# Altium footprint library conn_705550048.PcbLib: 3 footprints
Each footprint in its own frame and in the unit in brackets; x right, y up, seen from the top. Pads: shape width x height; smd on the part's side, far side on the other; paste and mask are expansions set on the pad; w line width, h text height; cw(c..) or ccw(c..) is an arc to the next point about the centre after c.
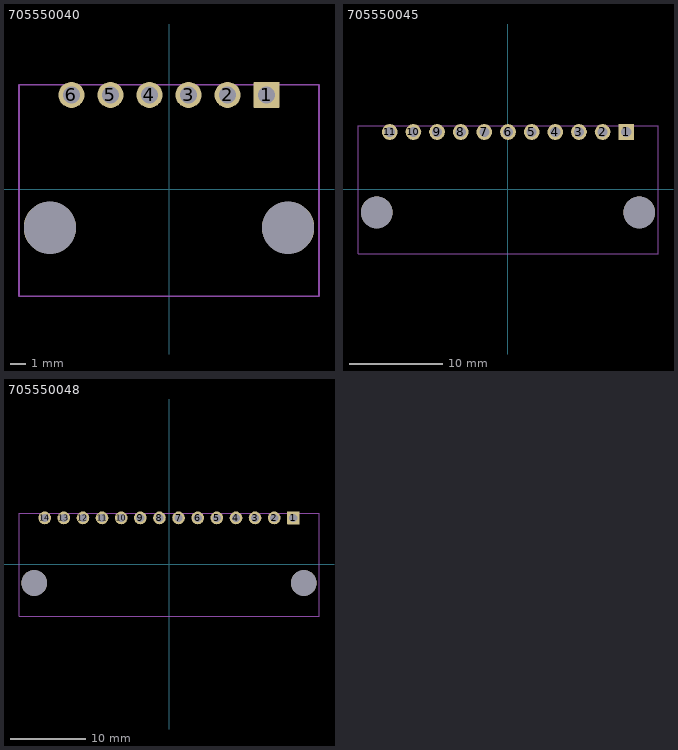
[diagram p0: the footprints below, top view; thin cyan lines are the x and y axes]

## 705550040 [mm]
height 1.1
pads (8):
  rrect6% 1.69x1.69 hole 1.09 paste-1000 mask+0: 1(6.35,6.145)
  round 1.69 hole 1.09 paste-1000 mask+0: 2(3.81,6.145) 3(1.27,6.145) 4(-1.27,6.145) 5(-3.81,6.145) 6(-6.35,6.145)
  round 3.4 hole 3.4 unplated paste-1000 mask+0: ""(-7.75,-2.495) ""(7.75,-2.495)
Mechanical 5:
  lines w0.1: -9.76,-6.945 -9.76,6.795 9.76,6.795 9.76,-6.945 -9.76,-6.945
  text ".Designator" at 0,0.022 h0.5
3D body "705550040.stp": height 7.12, standoff -3.17, extent -9.525,-6.789 9.525,6.8

## 705550045 [mm]
height 1.1
pads (13):
  rrect6% 1.69x1.69 hole 1.09 paste-1000 mask+0: 1(12.71,6.145)
  round 1.69 hole 1.09 paste-1000 mask+0: 2(10.17,6.145) 3(7.63,6.145) 4(5.09,6.145) 5(2.55,6.145) 6(0.01,6.145) 7(-2.53,6.145) 8(-5.07,6.145) 9(-7.61,6.145) 10(-10.15,6.145) 11(-12.69,6.145)
  round 3.4 hole 3.4 unplated paste-1000 mask+0: ""(-14.09,-2.495) ""(14.11,-2.495)
Mechanical 5:
  lines w0.1: -16.1,-6.945 -16.1,6.795 16.12,6.795 16.12,-6.945 -16.1,-6.945
  text ".Designator" at -3.8,0.022 h0.5
3D body "705550045.stp": height 7.11, standoff -3.17, extent -15.875,-6.789 15.875,6.8

## 705550048 [mm]
height 1.1
pads (16):
  rrect6% 1.69x1.69 hole 1.09 paste-1000 mask+0: 1(16.51,6.145)
  round 1.69 hole 1.09 paste-1000 mask+0: 2(13.97,6.145) 3(11.43,6.145) 4(8.89,6.145) 5(6.35,6.145) 6(3.81,6.145) 7(1.27,6.145) 8(-1.27,6.145) 9(-3.81,6.145) 10(-6.35,6.145) 11(-8.89,6.145) 12(-11.43,6.145) 13(-13.97,6.145) 14(-16.51,6.145)
  round 3.4 hole 3.4 unplated paste-1000 mask+0: ""(-17.91,-2.495) ""(17.91,-2.495)
Mechanical 5:
  lines w0.1: -19.92,-6.945 -19.92,6.795 19.92,6.795 19.92,-6.945 -19.92,-6.945
  text ".Designator" at 0,0.022 h0.5
3D body "705550048.stp": height 7.11, standoff -3.17, extent -19.685,-6.794 19.685,6.795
